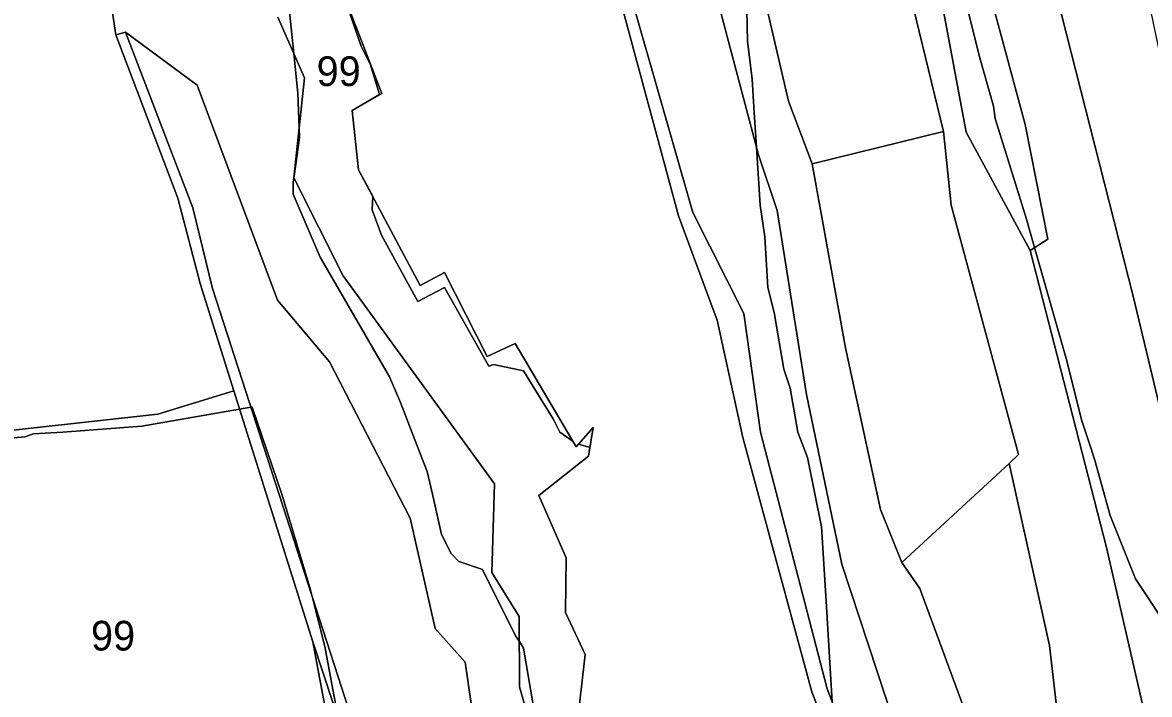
# Model space of a CAD drawing. Extents: x -502026 to -497664, y -1143484 to -1138019.
# Drawn here: x -498865.2 to -498561.6, y -1139733.2 to -1139552.1 of the extents above; entities that cross this region are included whole.
import ezdxf

# ---------------------------------------------------------------- set-up
doc = ezdxf.new("R2010")
doc.units = 0
for name, color, linetype in [('37', 7, 'Continuous'), ('43', 7, 'Continuous'), ('55', 7, 'Continuous'), ('62', 7, 'Continuous'), ('7', 7, 'Continuous')]:
    doc.layers.add(name, color=color, linetype=linetype)

msp = doc.modelspace()

# ---------------------------------------------------------------- linework, layer by layer
at = {"layer": '37'}
for points in [[(-498875.41, -1139375.15), (-498875.73, -1139387.46), (-498871.15, -1139405.99), (-498868.95, -1139414.87), (-498855.49, -1139489.49), (-498842.04, -1139542.22), (-498840.04, -1139555.4), (-498823.37, -1139599.43), (-498817.39, -1139622.43), (-498808.28, -1139651.41), (-498828.74, -1139657.68), (-498899.47, -1139665.52), (-498914.39, -1139582.18), (-498925.22, -1139532.99), (-498933.55, -1139482.92), (-498940.43, -1139455.37), (-498958.45, -1139372.23), (-498930.12, -1139378.48), (-498891.99, -1139382.44), (-498882.2, -1139384.94), (-498880.95, -1139374.73)], [(-498617.15, -1139581.5), (-498652.49, -1139590.15), (-498658.88, -1139573.29), (-498667.9, -1139534.19), (-498677.81, -1139503.51), (-498662.07, -1139496.35), (-498642.86, -1139488.67), (-498629.29, -1139531.17)], [(-498686.87, -1139507.63), (-498678.6, -1139543.53), (-498666.96, -1139587.76), (-498661.88, -1139602.74), (-498653.99, -1139652.37), (-498644.54, -1139698.09), (-498625.44, -1139755.93), (-498623.42, -1139762.03), (-498626.05, -1139772.41), (-498633.32, -1139768.98), (-498635.8, -1139764.42), (-498648.45, -1139731.67), (-498666.42, -1139662.49), (-498670.89, -1139630.53), (-498684.63, -1139603.27), (-498709.54, -1139516.32), (-498688.77, -1139500.66)], [(-498652.49, -1139590.15), (-498643.47, -1139639.77), (-498634.08, -1139683.38), (-498628.33, -1139697.65), (-498623.52, -1139704.64), (-498607.86, -1139747.09), (-498620.86, -1139752.54), (-498625.44, -1139755.93), (-498644.54, -1139698.09), (-498653.99, -1139652.37), (-498661.88, -1139602.74), (-498666.96, -1139587.76), (-498678.6, -1139543.53), (-498686.87, -1139507.63), (-498677.81, -1139503.51), (-498667.9, -1139534.19), (-498658.88, -1139573.29)], [(-498599.45, -1139670.96), (-498628.33, -1139697.65), (-498634.08, -1139683.38), (-498643.47, -1139639.77), (-498652.49, -1139590.15), (-498617.15, -1139581.5), (-498615.07, -1139601.31), (-498596.87, -1139668.57)], [(-498586.47, -1139737.88), (-498607.86, -1139747.09), (-498623.52, -1139704.64), (-498628.33, -1139697.65), (-498599.45, -1139670.96), (-498588.6, -1139720.05)]]:
    msp.add_lwpolyline(points, close=True, dxfattribs=at)
for points in [[(-498715.75, -1139740.5), (-498713.67, -1139722.44), (-498718.94, -1139711.1), (-498718.78, -1139696.4), (-498726.13, -1139679.62), (-498712.72, -1139668.96), (-498711.46, -1139661.22), (-498716.07, -1139666.43), (-498732.52, -1139638.62), (-498740.02, -1139642.14), (-498751.52, -1139619.45), (-498758.07, -1139622.97), (-498774.68, -1139591.81), (-498776.44, -1139575.83), (-498768.45, -1139571.2), (-498791.77, -1139510.64)], [(-498707.6, -1139533.2), (-498688.46, -1139604.23), (-498680.3, -1139626.33), (-498678.08, -1139632.35), (-498671.21, -1139663.99), (-498652.61, -1139732.47), (-498640.67, -1139763.31)]]:
    msp.add_lwpolyline(points, dxfattribs=at)
at = {"layer": '43'}
for points in [[(-498791.77, -1139510.64), (-498768.45, -1139571.2), (-498776.44, -1139575.83), (-498774.68, -1139591.81), (-498758.07, -1139622.97), (-498751.52, -1139619.45), (-498740.02, -1139642.14), (-498732.52, -1139638.62), (-498716.07, -1139666.43), (-498711.46, -1139661.22), (-498712.72, -1139668.96), (-498726.13, -1139679.62), (-498718.78, -1139696.4), (-498718.94, -1139711.1), (-498713.67, -1139722.44), (-498715.75, -1139740.5)], [(-498739.86, -1139766.54), (-498745.93, -1139724.52), (-498754.08, -1139715.41), (-498760.79, -1139685.69), (-498782.52, -1139643.58), (-498796.56, -1139626.9), (-498818.16, -1139568.98), (-498837.48, -1139554.68), (-498840.04, -1139555.4), (-498842.04, -1139542.22)], [(-498724.69, -1139754.37), (-498731.32, -1139731.14), (-498731.4, -1139712.19), (-498738.75, -1139700.36), (-498738.11, -1139676.43), (-498778.83, -1139620.35), (-498792.09, -1139593.98), (-498789.21, -1139566.98), (-498796.4, -1139550.68)], [(-498796.4, -1139550.68), (-498789.21, -1139566.98), (-498792.09, -1139593.98), (-498778.83, -1139620.35), (-498738.11, -1139676.43), (-498738.75, -1139700.36), (-498731.4, -1139712.19), (-498731.32, -1139731.14), (-498724.69, -1139754.37), (-498723.42, -1139768.3), (-498726.25, -1139783.77), (-498724.21, -1139797.38), (-498712.04, -1139824.34), (-498706.54, -1139841.7), (-498676.94, -1139836.36), (-498674.5, -1139843.51), (-498702.08, -1139848.49), (-498683.31, -1139899.39), (-498672.5, -1139909.81), (-498663.04, -1139937.41), (-498671.08, -1139958.4), (-498644.57, -1140057.16)]]:
    msp.add_lwpolyline(points, dxfattribs=at)
for points in [[(-498766.35, -1139771.24), (-498814.05, -1139623.81), (-498819.34, -1139602.08), (-498837.48, -1139554.68), (-498818.16, -1139568.98), (-498796.56, -1139626.9), (-498782.52, -1139643.58), (-498760.79, -1139685.69), (-498754.08, -1139715.41), (-498745.93, -1139724.52), (-498739.86, -1139766.54), (-498744.18, -1139776.93)], [(-498787.04, -1139718.98), (-498778.97, -1139761.69), (-498773.3, -1139800.73), (-498794.83, -1139788.43), (-498818.23, -1139786.24), (-498827.65, -1139785.68), (-498848.01, -1139771.44), (-498862.83, -1139774.94), (-498869.91, -1139776.6), (-498880.62, -1139742.54), (-498891.03, -1139708.74), (-498899.47, -1139665.52), (-498828.74, -1139657.68), (-498808.28, -1139651.41)], [(-498770.51, -1139769.15), (-498778.97, -1139761.69), (-498787.04, -1139718.98)]]:
    msp.add_lwpolyline(points, close=True, dxfattribs=at)
at = {"layer": '55'}
for points in [[(-498709.54, -1139516.32), (-498684.63, -1139603.27), (-498670.89, -1139630.53), (-498666.42, -1139662.49), (-498648.45, -1139731.67), (-498635.8, -1139764.42), (-498633.32, -1139768.98), (-498626.05, -1139772.41), (-498623.41, -1139785.38), (-498625.92, -1139790.31), (-498636.12, -1139810.39), (-498642.74, -1139830.04), (-498644.26, -1139843.3), (-498639.91, -1139872.46), (-498617.87, -1139937.49), (-498614.84, -1139940.05), (-498605.77, -1139974.16), (-498571.82, -1140072.9)], [(-498621.49, -1139525.39), (-498611.01, -1139581.68), (-498593.78, -1139613.51), (-498573.17, -1139693.64), (-498559.58, -1139753.1)], [(-498554.81, -1139774.16), (-498570.65, -1139759.26), (-498578.62, -1139745.23), (-498582.18, -1139740.42), (-498585.95, -1139742.19), (-498586.47, -1139737.88), (-498588.6, -1139720.05), (-498599.45, -1139670.96), (-498596.87, -1139668.57), (-498615.07, -1139601.31), (-498617.15, -1139581.5), (-498629.29, -1139531.17)], [(-498579.78, -1140063.88), (-498605.69, -1139986.46), (-498617.75, -1139942.21), (-498621.06, -1139939.57), (-498644.2, -1139870.82), (-498647.69, -1139844.66), (-498645.94, -1139827.81), (-498639.63, -1139809.67), (-498627.81, -1139785.59), (-498629.09, -1139778.72), (-498635.08, -1139772.01), (-498640.67, -1139763.31), (-498652.61, -1139732.47), (-498671.21, -1139663.99), (-498678.08, -1139632.35), (-498680.3, -1139626.33), (-498688.46, -1139604.23), (-498707.6, -1139533.2)], [(-498677.51, -1140043.55), (-498693.22, -1139984.36), (-498712.25, -1139972.61), (-498712.79, -1139970.57), (-498730.28, -1139904.44), (-498757.03, -1139810.03), (-498770.51, -1139769.15), (-498787.04, -1139718.98), (-498808.28, -1139651.41), (-498817.39, -1139622.43), (-498823.37, -1139599.43), (-498840.04, -1139555.4), (-498837.48, -1139554.68), (-498819.34, -1139602.08), (-498814.05, -1139623.81), (-498766.35, -1139771.24), (-498753.21, -1139811.87), (-498723.93, -1139917.36), (-498710.5, -1139968.39), (-498689.86, -1139982.26), (-498673.72, -1140043.63)]]:
    msp.add_lwpolyline(points, dxfattribs=at)
at = {"layer": '62'}
for points in [[(-498556.47, -1139715.62), (-498562, -1139707.12), (-498565.41, -1139702), (-498572.19, -1139685), (-498576.44, -1139669.75), (-498577.9, -1139665.36), (-498579.84, -1139659.5), (-498584.09, -1139642.62), (-498592.56, -1139612.73), (-498594.72, -1139605.12), (-498603.22, -1139578), (-498603.62, -1139574.62), (-498607.47, -1139561), (-498618.5, -1139516.75)], [(-498618.5, -1139516.75), (-498607.47, -1139561), (-498603.62, -1139574.62), (-498603.22, -1139578), (-498594.72, -1139605.12), (-498592.56, -1139612.73), (-498584.09, -1139642.62), (-498579.84, -1139659.5), (-498577.9, -1139665.36), (-498576.44, -1139669.75), (-498572.19, -1139685), (-498565.41, -1139702), (-498562, -1139707.12), (-498556.47, -1139715.62)], [(-498793.97, -1139542.25), (-498792.1, -1139560.43), (-498791, -1139571.12), (-498790.66, -1139580.54), (-498790.56, -1139583.12), (-498791.97, -1139592.84), (-498792.28, -1139595), (-498792.28, -1139598.37), (-498785.06, -1139615.37), (-498766.37, -1139647.62), (-498763.37, -1139654.5), (-498759.56, -1139664.62), (-498756.16, -1139673.12), (-498754.79, -1139679.24), (-498752.34, -1139690.12), (-498749.78, -1139695.25), (-498747.66, -1139697.37), (-498741.28, -1139699.5), (-498732.37, -1139717.37), (-498731.37, -1139718.97), (-498730.25, -1139720.75), (-498726.44, -1139742.87)], [(-498726.44, -1139742.87), (-498730.25, -1139720.75), (-498731.37, -1139718.97), (-498732.37, -1139717.37), (-498741.28, -1139699.5), (-498747.66, -1139697.37), (-498749.78, -1139695.25), (-498752.34, -1139690.12), (-498754.79, -1139679.24), (-498756.16, -1139673.12), (-498759.56, -1139664.62), (-498763.37, -1139654.5), (-498766.37, -1139647.62), (-498785.06, -1139615.37), (-498792.28, -1139598.37), (-498792.28, -1139595), (-498791.97, -1139592.84), (-498790.56, -1139583.12), (-498790.66, -1139580.54), (-498791, -1139571.12), (-498792.1, -1139560.43), (-498793.97, -1139542.25)], [(-498715.75, -1139740.5), (-498713.67, -1139722.44), (-498718.94, -1139711.1), (-498718.78, -1139696.4), (-498726.13, -1139679.62), (-498712.72, -1139668.96), (-498712.34, -1139666.64), (-498713.79, -1139666.22), (-498715.45, -1139665.73), (-498716.07, -1139666.43), (-498716.91, -1139665.01), (-498720.47, -1139662.5), (-498722.19, -1139659.12), (-498730.25, -1139646), (-498738.31, -1139644.25), (-498739.59, -1139644.75), (-498751.5, -1139623.5), (-498758.72, -1139627.25), (-498768.5, -1139609.37), (-498771.03, -1139602.62), (-498770.88, -1139598.93), (-498774.68, -1139591.81), (-498776.44, -1139575.83), (-498769.04, -1139571.54), (-498771.47, -1139563.5), (-498774, -1139558.5), (-498778.69, -1139544.87)], [(-498778.69, -1139544.87), (-498774, -1139558.5), (-498771.47, -1139563.5), (-498769.04, -1139571.54), (-498776.44, -1139575.83), (-498774.68, -1139591.81), (-498770.88, -1139598.93), (-498771.03, -1139602.62), (-498768.5, -1139609.37), (-498758.72, -1139627.25), (-498751.5, -1139623.5), (-498739.59, -1139644.75), (-498738.31, -1139644.25), (-498730.25, -1139646), (-498722.19, -1139659.12), (-498720.47, -1139662.5), (-498716.91, -1139665.01), (-498716.07, -1139666.43), (-498715.45, -1139665.73), (-498713.79, -1139666.22), (-498712.34, -1139666.64), (-498712.72, -1139668.96), (-498726.13, -1139679.62), (-498718.78, -1139696.4), (-498718.94, -1139711.1), (-498713.67, -1139722.44), (-498715.75, -1139740.5)], [(-498647.09, -1139735.18), (-498648.73, -1139708.05), (-498649.94, -1139688), (-498653.78, -1139669.37), (-498656.31, -1139662.5), (-498658.44, -1139650.62), (-498660.16, -1139645.5), (-498662.69, -1139630.25), (-498664.41, -1139623.5), (-498665.25, -1139609.87), (-498666.53, -1139601.37), (-498667.51, -1139585.66), (-498668.09, -1139576.36), (-498668.66, -1139567.37), (-498669.91, -1139557.12), (-498670.12, -1139548.89)], [(-498670.12, -1139548.89), (-498669.91, -1139557.12), (-498668.66, -1139567.37), (-498668.09, -1139576.36), (-498667.51, -1139585.66), (-498666.53, -1139601.37), (-498665.25, -1139609.87), (-498664.41, -1139623.5), (-498662.69, -1139630.25), (-498660.16, -1139645.5), (-498658.44, -1139650.62), (-498656.31, -1139662.5), (-498653.78, -1139669.37), (-498649.94, -1139688), (-498648.73, -1139708.05), (-498647.09, -1139735.18)], [(-498780.1, -1139740.04), (-498783.78, -1139720.25), (-498786.96, -1139707.55), (-498787.23, -1139706.46), (-498787.59, -1139705), (-498795.25, -1139679.5), (-498803.31, -1139655.75), (-498803.69, -1139655.81), (-498806.73, -1139656.34), (-498833.06, -1139660.87), (-498854.31, -1139662.5), (-498862.37, -1139663), (-498864.5, -1139663.75), (-498884.91, -1139665.5)], [(-498884.91, -1139665.5), (-498864.5, -1139663.75), (-498862.37, -1139663), (-498854.31, -1139662.5), (-498833.06, -1139660.87), (-498806.73, -1139656.34), (-498803.69, -1139655.81), (-498803.31, -1139655.75), (-498795.25, -1139679.5), (-498787.59, -1139705), (-498787.23, -1139706.46), (-498786.96, -1139707.55), (-498783.78, -1139720.25), (-498780.1, -1139740.04)]]:
    msp.add_lwpolyline(points, dxfattribs=at)
at = {"layer": '7'}
for points in [[(-498499.71, -1139807.05), (-498513.49, -1139808.39), (-498526.96, -1139778.88), (-498542.88, -1139733.02), (-498554.26, -1139675.02), (-498566.01, -1139625.85), (-498590.48, -1139529.74), (-498614.94, -1139420.38), (-498602.65, -1139414.89), (-498591.97, -1139410.26), (-498580.22, -1139458.73), (-498558.85, -1139560.83), (-498544.11, -1139626.02), (-498529.15, -1139676.01), (-498510.77, -1139765.85)], [(-498513.49, -1139808.39), (-498559.58, -1139753.1), (-498573.17, -1139693.64), (-498593.78, -1139613.51), (-498589.05, -1139610.48), (-498595.08, -1139579.6), (-498609.4, -1139526.58), (-498631.58, -1139431.63), (-498614.94, -1139420.38), (-498590.48, -1139529.74), (-498566.01, -1139625.85), (-498554.26, -1139675.02), (-498542.88, -1139733.02), (-498526.96, -1139778.88)], [(-498593.78, -1139613.51), (-498611.01, -1139581.68), (-498621.49, -1139525.39), (-498642.94, -1139439.3), (-498631.58, -1139431.63), (-498609.4, -1139526.58), (-498595.08, -1139579.6), (-498589.05, -1139610.48)]]:
    msp.add_lwpolyline(points, close=True, dxfattribs=at)

# ---------------------------------------------------------------- texts
at = {"layer": '62'}
for p in [(-498786, -1139569.22), (-498846.76, -1139721.36)]:
    msp.add_text('99', height=8, dxfattribs=at).set_placement(p)

doc.saveas('drawing.dxf')
